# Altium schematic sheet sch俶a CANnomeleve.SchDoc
size A4
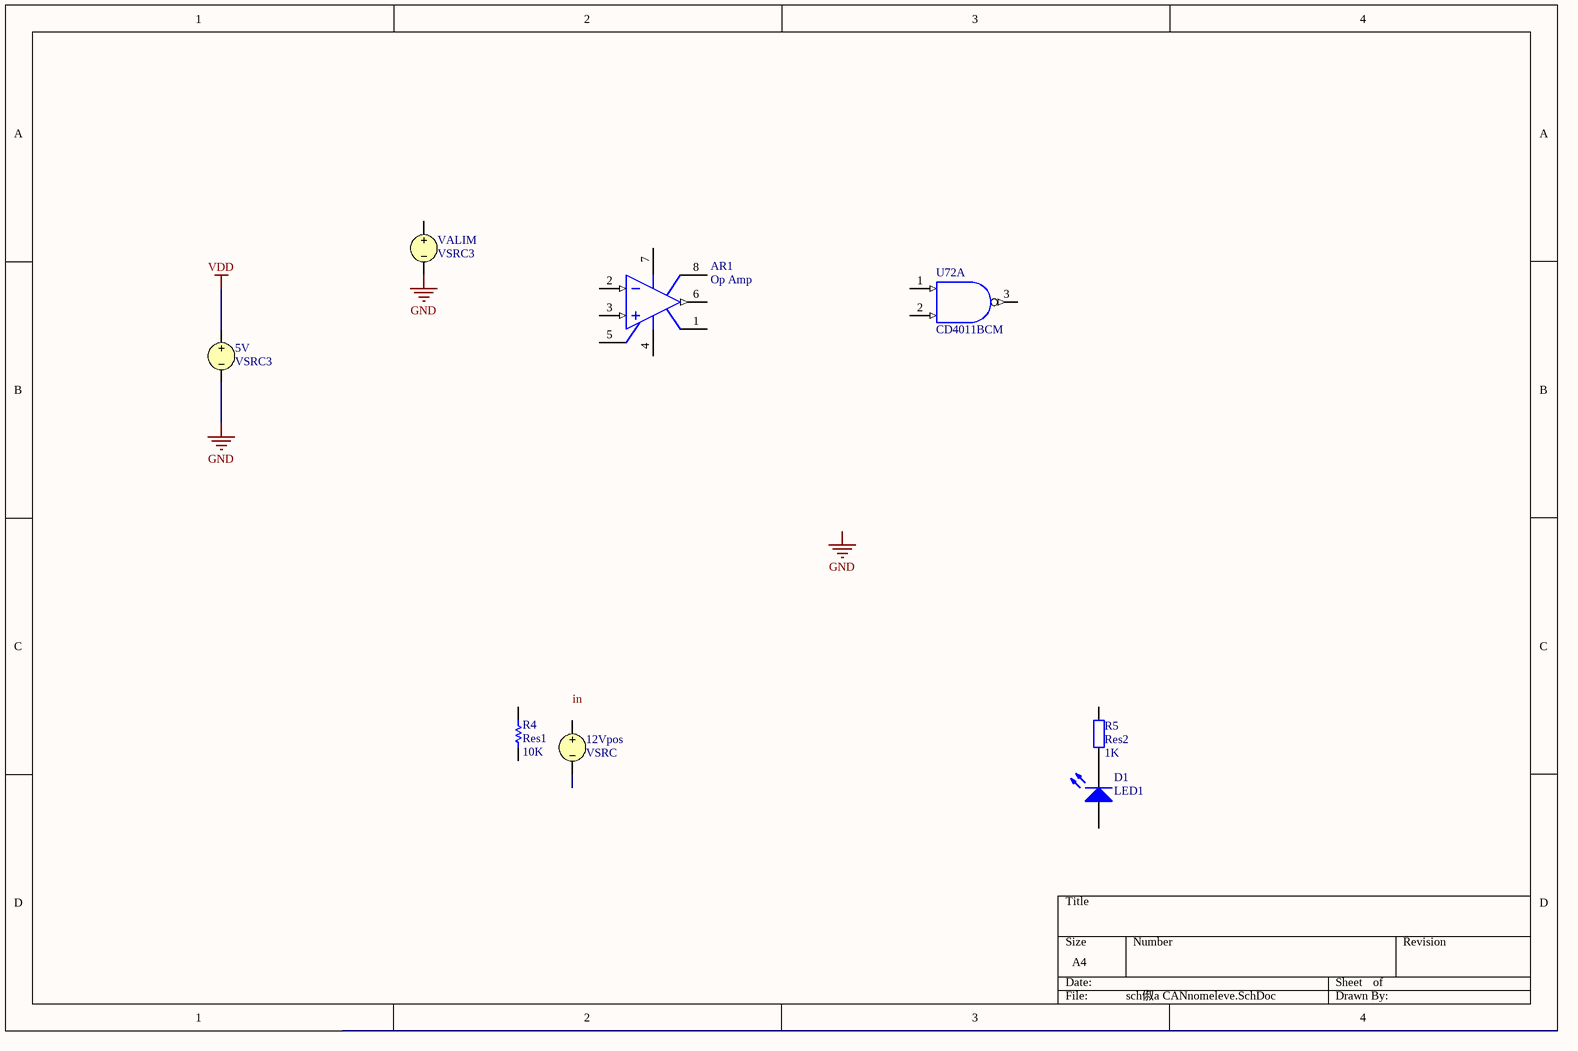
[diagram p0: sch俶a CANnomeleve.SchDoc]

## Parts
5V  VSRC3
12Vpos  VSRC
AR1  Op Amp  [H-08A]
D1  LED1  [LED-1]
R4  Res1  value 10K  [AXIAL-0.3]
R5  Res2  value 1K  [AXIAL-0.4]
U72  CD4011BCM  [M14A_N]  (part A of 4)
VALIM  VSRC3

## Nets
GND: 5V.2 U72.7(GND) VALIM.2
VDD: 5V.1 U72.14(VDD)
NetD1_2: D1.2(K) R5.1

Not connected (* = marked no-connect by the designer): 12Vpos 1 2; AR1 1(OS_NUL) 2(IN-) 3(IN+) 4(V-) 5(OS_NUL) 6(OUT) 7(V+) 8(TAB); D1 1(A); R4 1 2; R5 2; U72 1(A) 2(B) 3(J); VALIM 1

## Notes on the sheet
- Labels drawn without touching a wire or pin: GND, in

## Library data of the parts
5V = VSRC: Voltage Source; Note: PCB Footprint - Not required; Value: +5
12Vpos = VSRC: Voltage Source; Note: PCB Footprint - Not required; Value: 10
AR1 = Op Amp: FET Operational Amplifier
D1 = LED1: Typical RED GaAs LED
R4 = Res1: Resistor
R5 = Res2: Resistor
U72 = CD4011BCM: Quad 2-Input NAND Buffered B series Gate, 14-Pin SOIC; IC_Technology: C
VALIM = VSRC: Voltage Source; Note: PCB Footprint - Not required; Value: +12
